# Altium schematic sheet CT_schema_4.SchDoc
size 187 x 159 mm
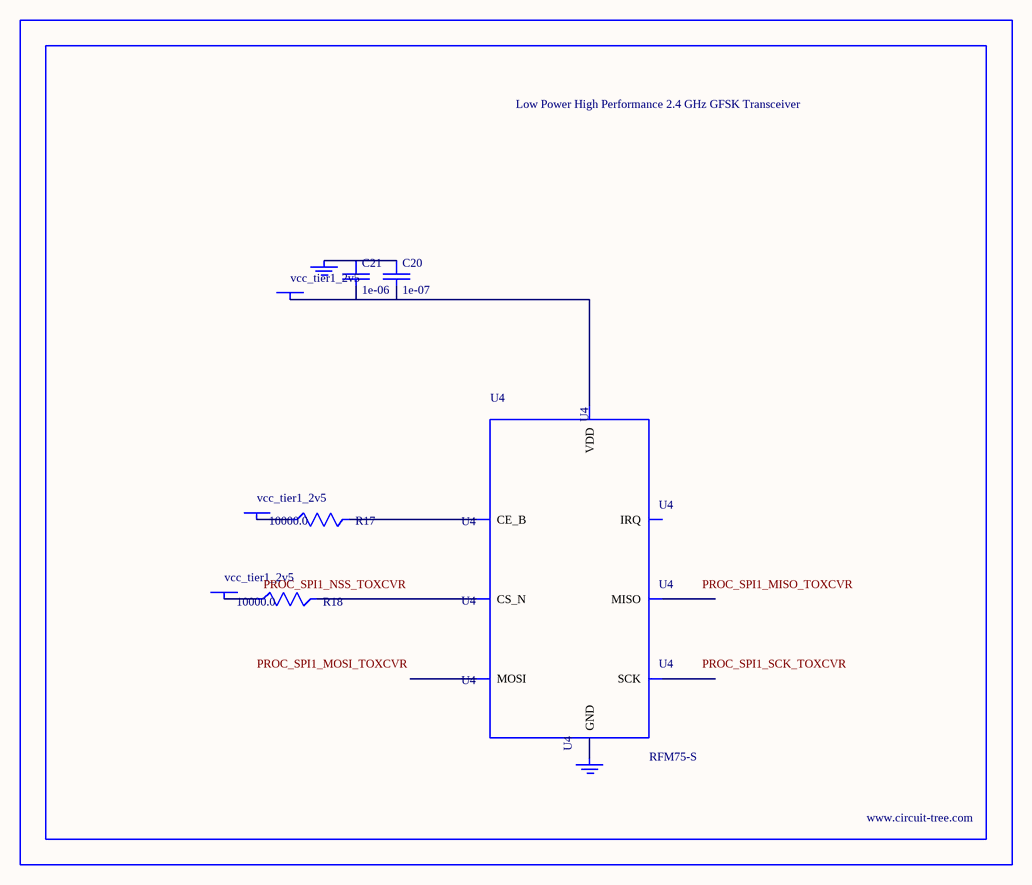
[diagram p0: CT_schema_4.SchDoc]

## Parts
BORDER3  (no value)
C20  1e-07  [C0402]
C21  1e-06  [C0603]
GND_INSTANCE_3_0  (no value)
GND_INSTANCE_3_1  (no value)
POWER_INSTANCE_3_0  vcc_tier1_2v5
POWER_INSTANCE_3_1  vcc_tier1_2v5
POWER_INSTANCE_3_2  vcc_tier1_2v5
R17  10000.0  [R0603]
R18  10000.0  [R0603]
U4  RFM75-S  [RFM75-S]

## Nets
NetC20_1: C20.1 C21.1 GND_INSTANCE_3_0.0(GND)
NetC20_2: C20.2 C21.2 POWER_INSTANCE_3_0.0(PWR) U4.2(VDD)
NetGND_INSTANCE_3_1_0: GND_INSTANCE_3_1.0(GND) U4.1(GND)
NetPOWER_INSTANCE_3_1_0: POWER_INSTANCE_3_1.0(PWR) R17.1
NetPOWER_INSTANCE_3_2_0: POWER_INSTANCE_3_2.0(PWR) R18.1
NetR17_2: R17.2 U4.3(CE_B)
NetR18_2: R18.2 U4.4(CS_N)

Not connected (* = marked no-connect by the designer): U4 5(SCK) 6(MOSI) 7(MISO) 8(IRQ)

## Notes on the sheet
- Labels drawn without touching a wire or pin: PROC_SPI1_MISO_TOXCVR, PROC_SPI1_MOSI_TOXCVR, PROC_SPI1_NSS_TOXCVR, PROC_SPI1_SCK_TOXCVR

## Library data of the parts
BORDER3 = BORDER_PAGE3
C20 = C0402C104K3RACTU
C21 = C0603C105K3RACTU
GND_INSTANCE_3_0 GND_INSTANCE_3_1 = GND
POWER_INSTANCE_3_0-POWER_INSTANCE_3_2 = PWR
R17 R18 = RC0603JR-0710KL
